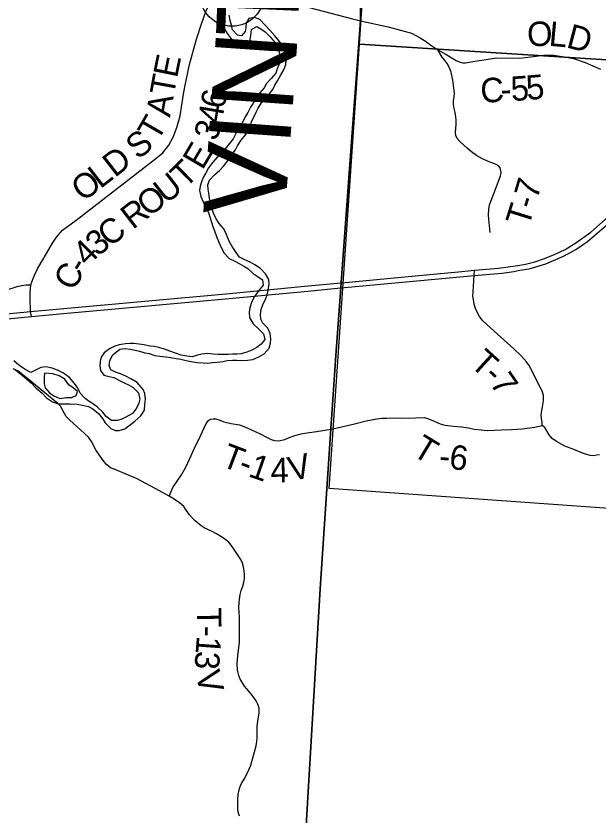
# Model space of a CAD drawing. Extents: x 0 to 34, y 0 to 22.
# Drawn here: x 3.455 to 4.807, y 17.141 to 18.997 of the extents above; entities that cross this region are included whole.
import ezdxf

# ---------------------------------------------------------------- set-up
doc = ezdxf.new("R2010")
doc.units = 0
for name, color, linetype in [('GM_X_Corporation', 7, 'Continuous'), ('GM_X_County_Road', 7, 'Continuous'), ('GM_X_County_Road_Text', 7, 'Continuous'), ('GM_X_County_Text', 7, 'Continuous'), ('GM_X_Major_River', 7, 'Continuous'), ('GM_X_State_Route', 7, 'Continuous'), ('GM_X_Township_Road', 7, 'Continuous'), ('GM_X_Township_Road_Text', 7, 'Continuous'), ('GM_X_Township_Text', 7, 'Continuous'), ('GM_X_Unincorporated', 7, 'Continuous')]:
    doc.layers.add(name, color=color, linetype=linetype)

msp = doc.modelspace()

# ---------------------------------------------------------------- linework, layer by layer
at = {"layer": 'GM_X_Corporation'}
msp.add_lwpolyline([(4.1215, 17.0136), (4.1603, 17.6679), (4.1853, 18.0392), (4.1964, 18.2095), (4.2079, 18.3668), (4.2088, 18.3789), (4.2282, 18.6426), (4.2537, 18.9868), (4.2536, 19.0552), (4.2737, 19.3421), (4.2893, 19.6309), (4.3029, 19.8336), (4.3134, 19.9898), (4.3401, 20.3869), (4.364, 20.7926), (4.3772, 20.9), (2.1, 20.9), (2.1, 14.9497)], dxfattribs=at)
for points in [[(5.342, 19.878), (5.2756, 18.8667), (4.2512, 18.9319), (4.3184, 19.9368)], [(4.2512, 18.9319), (5.2756, 18.8667), (5.2491, 18.5021), (5.2146, 18.0305), (5.1989, 17.8285), (4.1811, 17.9012)]]:
    msp.add_lwpolyline(points, close=True, dxfattribs=at)
at = {"layer": 'GM_X_County_Road'}
for points in [[(3.9168, 19.0437), (3.9261, 19.0496), (3.9355, 19.0554), (3.9447, 19.06), (3.9516, 19.0629), (3.9608, 19.0652), (3.9701, 19.0674), (3.9771, 19.0681), (3.9835, 19.0677), (3.992, 19.0674), (4.001, 19.065), (4.0168, 19.0614), (4.0442, 19.0511), (4.0739, 19.0399), (4.1079, 19.0272), (4.1213, 19.0223), (4.1351, 19.017), (4.2352, 18.9904), (4.2539, 18.9862)], [(3.5195, 18.4353), (3.5205, 18.4371), (3.5398, 18.4705), (3.5489, 18.484), (3.5628, 18.5), (3.5942, 18.5239), (3.6761, 18.5868), (3.7791, 18.6664), (3.7951, 18.68), (3.809, 18.6975), (3.8193, 18.716), (3.8275, 18.7388), (3.8353, 18.7655), (3.8433, 18.8163), (3.8461, 18.8329), (3.8573, 18.885), (3.8738, 18.9436), (3.8854, 18.9794), (3.8952, 19.0076), (3.9018, 19.0226), (3.9168, 19.0437)], [(4.2539, 18.9862), (4.3184, 18.9718), (4.3466, 18.9647), (4.372, 18.9572), (4.392, 18.9469), (4.4049, 18.9389), (4.4196, 18.9281), (4.4329, 18.9187), (4.4506, 18.9094), (4.4754, 18.8944), (4.4852, 18.89), (4.4916, 18.8889), (4.4971, 18.8887), (4.5192, 18.8922), (4.5407, 18.8958), (4.5545, 18.8982), (4.5694, 18.8999), (4.6224, 18.8994), (4.6356, 18.9007), (4.6552, 18.9033), (4.6788, 18.9062), (4.7019, 18.9062), (4.7269, 18.9029), (4.7478, 18.8988), (4.7752, 18.8893), (4.8104, 18.8742)], [(3.4904, 18.3), (3.4888, 18.3117), (3.4884, 18.3153), (3.4878, 18.3385), (3.4873, 18.3557), (3.4892, 18.3733), (3.4934, 18.3842), (3.4978, 18.3962), (3.5047, 18.4109), (3.5134, 18.425), (3.5195, 18.4353)]]:
    msp.add_lwpolyline(points, dxfattribs=at)
at = {"layer": 'GM_X_Major_River'}
for points in [[(3.9277, 19.0051), (3.9315, 18.9896), (3.9345, 18.9797), (3.9387, 18.9668), (3.9448, 18.9569), (3.9512, 18.9471), (3.9615, 18.9334), (3.9744, 18.9239), (3.988, 18.9265), (3.9975, 18.9387), (3.9998, 18.9523), (4.0014, 18.9656), (4.0131, 18.9732), (4.0226, 18.9675), (4.0325, 18.9603), (4.0442, 18.9489), (4.0556, 18.9352), (4.0621, 18.9254), (4.0655, 18.9125), (4.0677, 18.8988), (4.0662, 18.8882), (4.0609, 18.8745), (4.0574, 18.8643), (4.0464, 18.8525), (4.0362, 18.8404), (4.0301, 18.8309), (4.0198, 18.818), (4.0111, 18.8055), (4.0046, 18.7949), (3.9985, 18.7854), (3.9924, 18.7736), (3.9867, 18.7634), (3.9791, 18.7486), (3.9734, 18.7391), (3.9658, 18.7262), (3.9582, 18.7126), (3.9498, 18.7012), (3.9403, 18.6894), (3.9259, 18.675), (3.9167, 18.6644), (3.9084, 18.6542), (3.9015, 18.6447), (3.8947, 18.6322), (3.8886, 18.6223), (3.8848, 18.6128), (3.8817, 18.6022), (3.8806, 18.5927), (3.8832, 18.5787), (3.8889, 18.5661), (3.8954, 18.5525), (3.901, 18.5411), (3.9045, 18.5312), (3.9082, 18.5191), (3.9116, 18.5092), (3.9154, 18.499), (3.92, 18.4857), (3.9253, 18.4724), (3.9313, 18.4583), (3.9374, 18.447), (3.9495, 18.4344), (3.9624, 18.4283), (3.9723, 18.4234), (3.9833, 18.4169), (3.9928, 18.4116), (4.0046, 18.4002), (4.0167, 18.3919), (4.0262, 18.385), (4.0281, 18.3729), (4.0178, 18.36), (4.0079, 18.3463), (4.0018, 18.3346), (3.9973, 18.3205), (3.9957, 18.3099), (3.9965, 18.2978), (4.0048, 18.283), (4.0173, 18.2712), (4.0291, 18.2602), (4.0317, 18.2469), (4.0238, 18.2355), (4.0135, 18.2279), (4.0021, 18.2223), (3.9899, 18.2173), (3.9774, 18.2132), (3.9672, 18.2128), (3.9573, 18.2124), (3.947, 18.2121), (3.9239, 18.2121), (3.9121, 18.2128), (3.8996, 18.214), (3.8859, 18.2125), (3.8756, 18.2102), (3.8635, 18.2068), (3.851, 18.2083), (3.8381, 18.2106), (3.8248, 18.2148), (3.8115, 18.2194), (3.7993, 18.2243)], [(3.8263, 18.2027), (3.8373, 18.2007), (3.8494, 18.1981), (3.865, 18.195), (3.876, 18.1935), (3.8889, 18.1924), (3.8999, 18.192), (3.9109, 18.1935), (3.922, 18.1942), (3.9345, 18.1957), (3.9444, 18.1976), (3.9573, 18.1988), (3.9668, 18.1988), (3.9797, 18.198), (3.9914, 18.1984), (4.0044, 18.2006), (4.0177, 18.2067), (4.0302, 18.2131), (4.042, 18.2264), (4.045, 18.2378), (4.0462, 18.2477), (4.0443, 18.2606), (4.0386, 18.2731), (4.0276, 18.2845), (4.0227, 18.294), (4.0219, 18.3046), (4.0231, 18.3164), (4.0284, 18.3293), (4.0334, 18.3395), (4.0375, 18.3505), (4.0398, 18.3607), (4.0417, 18.3759), (4.0414, 18.3862), (4.0338, 18.3991), (4.022, 18.4116), (4.0088, 18.4203), (3.9978, 18.4264), (3.9856, 18.4317), (3.9735, 18.4378), (3.9655, 18.4485), (3.9564, 18.4625), (3.95, 18.4735), (3.9454, 18.4841), (3.9412, 18.4944), (3.9363, 18.5043), (3.9257, 18.516), (3.9189, 18.527), (3.9128, 18.5396), (3.9087, 18.5513), (3.906, 18.5616), (3.9034, 18.5749), (3.9019, 18.5859), (3.9003, 18.5957), (3.9, 18.6052), (3.9038, 18.6162), (3.9156, 18.6287), (3.9277, 18.6397), (3.9365, 18.6496), (3.9467, 18.6629), (3.954, 18.6739), (3.9639, 18.6868), (3.9688, 18.6962), (3.9772, 18.7095), (3.987, 18.7216), (3.9947, 18.7319), (3.9985, 18.7417), (4.0008, 18.7528), (4.0065, 18.7626), (4.0118, 18.774), (4.0164, 18.7835), (4.0232, 18.7952), (4.0323, 18.8047), (4.0418, 18.8157), (4.0502, 18.8271), (4.0548, 18.8369), (4.0616, 18.8468), (4.0692, 18.8608), (4.0764, 18.8722), (4.0806, 18.8851), (4.0818, 18.8961), (4.0807, 18.9098), (4.0742, 18.9257), (4.0659, 18.9383), (4.0549, 18.9515), (4.0435, 18.9641), (4.0325, 18.9762), (4.0204, 18.9891), (4.0082, 18.9941), (3.9949, 18.9918), (3.9885, 18.9804), (3.9877, 18.9709), (3.9862, 18.9615), (3.9778, 18.9516), (3.9683, 18.9531), (3.9573, 18.9653), (3.9547, 18.9759), (3.9516, 18.9865), (3.9494, 18.999)], [(3.7993, 18.2243), (3.7861, 18.2285), (3.7762, 18.2304), (3.7655, 18.2315), (3.7519, 18.2346), (3.7405, 18.2361), (3.7283, 18.2373), (3.7185, 18.2373), (3.7086, 18.2365), (3.6942, 18.2346), (3.6839, 18.2312), (3.6714, 18.2252), (3.6596, 18.2157), (3.6527, 18.2054), (3.6497, 18.1956), (3.6493, 18.1857), (3.6508, 18.1747), (3.6584, 18.1641), (3.6679, 18.1618), (3.6816, 18.1584), (3.6964, 18.1508), (3.7058, 18.1462), (3.7157, 18.1413), (3.7263, 18.1352), (3.7389, 18.123), (3.7419, 18.1086), (3.74, 18.0987), (3.7343, 18.0877), (3.7248, 18.0748), (3.7099, 18.0665), (3.7004, 18.062), (3.6906, 18.0585), (3.6761, 18.0589), (3.664, 18.0681), (3.6564, 18.0779), (3.6439, 18.0897), (3.6344, 18.0965), (3.6249, 18.1026), (3.6154, 18.1098), (3.6037, 18.1224), (3.5976, 18.1353), (3.59, 18.1455), (3.5794, 18.1577), (3.565, 18.1683), (3.551, 18.1752), (3.5388, 18.1801), (3.5244, 18.1835), (3.5126, 18.182), (3.5031, 18.1771), (3.4894, 18.1703), (3.4758, 18.1771), (3.4614, 18.1874), (3.4496, 18.1972)], [(3.4515, 18.1775), (3.461, 18.1703), (3.4742, 18.1593), (3.4898, 18.146), (3.5008, 18.1342), (3.5152, 18.1221), (3.5258, 18.1114), (3.5391, 18.1023), (3.5524, 18.0974), (3.5676, 18.0974), (3.5805, 18.0977), (3.5964, 18.0969), (3.6082, 18.0947), (3.6226, 18.0909), (3.6333, 18.0855), (3.6458, 18.0753), (3.6553, 18.0631), (3.6617, 18.0533), (3.6746, 18.0403), (3.6845, 18.0354), (3.694, 18.0358), (3.7069, 18.0396), (3.7164, 18.046), (3.7308, 18.057), (3.7445, 18.0699), (3.7525, 18.0828), (3.7536, 18.0961), (3.7548, 18.1086), (3.7537, 18.1215), (3.7499, 18.131), (3.7355, 18.1473), (3.7214, 18.1557), (3.7093, 18.1618), (3.6975, 18.1671), (3.6876, 18.1705), (3.6747, 18.1762), (3.6706, 18.1865), (3.6725, 18.1982), (3.6793, 18.2111), (3.6953, 18.224), (3.7082, 18.2255), (3.72, 18.2244), (3.731, 18.2221), (3.7412, 18.2198), (3.7534, 18.216), (3.7633, 18.2141), (3.7769, 18.2099), (3.7883, 18.2084), (3.8024, 18.2061), (3.8137, 18.2049), (3.8263, 18.2027)], [(3.5212, 18.1687), (3.5201, 18.1585), (3.5201, 18.1437), (3.5224, 18.1342), (3.5323, 18.1233), (3.5425, 18.1157), (3.5565, 18.11), (3.5713, 18.1123), (3.5842, 18.1123), (3.5893, 18.1145)], [(3.5893, 18.1145), (3.594, 18.1165), (3.5978, 18.126), (3.5872, 18.1347), (3.5777, 18.1415), (3.5678, 18.1544), (3.5546, 18.162), (3.5402, 18.1673), (3.5212, 18.1687)]]:
    msp.add_lwpolyline(points, dxfattribs=at)
at = {"layer": 'GM_X_State_Route'}
for points in [[(4.2081, 18.3662), (4.3931, 18.3837), (4.5176, 18.395), (4.5827, 18.4009), (4.6096, 18.4044), (4.6234, 18.4073), (4.6449, 18.411), (4.6841, 18.4225), (4.7244, 18.4397), (4.7534, 18.4558), (4.7801, 18.4743), (4.8348, 18.5208), (4.9519, 18.6244), (5.0029, 18.6705), (5.0757, 18.7346), (5.1002, 18.7546), (5.1243, 18.7729), (5.1439, 18.7876), (5.1801, 18.8119), (5.2033, 18.8272), (5.2305, 18.8431), (5.3733, 18.9281), (5.4683, 18.9843)], [(4.209, 18.3783), (4.2182, 18.3792), (4.3888, 18.3953), (4.4811, 18.4035), (4.5181, 18.4074), (4.5737, 18.4121), (4.6187, 18.4182), (4.6363, 18.4218), (4.6583, 18.4272), (4.6809, 18.4343), (4.7056, 18.4448), (4.7289, 18.4558), (4.7537, 18.4709), (4.7883, 18.4958), (4.8282, 18.531)], [(3.3064, 18.2941), (3.4888, 18.3117), (3.549, 18.3173), (3.9501, 18.3538), (4.1325, 18.3709), (4.209, 18.3783)], [(3.3079, 18.2824), (3.4904, 18.3), (3.5481, 18.3053), (3.9492, 18.3418), (4.1316, 18.3588), (4.2081, 18.3662)]]:
    msp.add_lwpolyline(points, dxfattribs=at)
at = {"layer": 'GM_X_Township_Road'}
for points in [[(4.5548, 18.4951), (4.5515, 18.5258), (4.5509, 18.5355), (4.5513, 18.5488), (4.5527, 18.5591), (4.5707, 18.6059), (4.5789, 18.6261), (4.5801, 18.6323), (4.5797, 18.6382), (4.5778, 18.645), (4.5739, 18.6496), (4.5685, 18.6524), (4.5485, 18.6608), (4.5354, 18.6668), (4.5232, 18.6735), (4.5113, 18.6819), (4.5011, 18.6907), (4.4934, 18.6978), (4.4839, 18.7062), (4.4781, 18.7131), (4.4753, 18.7202), (4.474, 18.7268), (4.4747, 18.737), (4.4757, 18.7456), (4.476, 18.7553), (4.4751, 18.7632), (4.4732, 18.7731), (4.4708, 18.7828), (4.4693, 18.7916), (4.4697, 18.8009), (4.4708, 18.8087), (4.4719, 18.819), (4.4704, 18.8302), (4.468, 18.8487), (4.4639, 18.8666), (4.4598, 18.8786), (4.4549, 18.8874), (4.4503, 18.8935), (4.443, 18.9019), (4.4329, 18.9187)], [(4.6667, 18.1436), (4.6616, 18.1539), (4.653, 18.1715), (4.645, 18.1863), (4.6386, 18.1951), (4.6267, 18.2089), (4.6093, 18.2249), (4.5639, 18.2661), (4.5375, 18.2902), (4.5301, 18.2998), (4.5245, 18.3103), (4.5206, 18.3183), (4.5172, 18.3289), (4.5157, 18.3396), (4.5145, 18.3476), (4.515, 18.3581), (4.5171, 18.3831), (4.5176, 18.395), (4.5181, 18.4074)], [(3.3454, 18.3407), (3.3656, 18.3459), (3.374, 18.3477), (3.4041, 18.354), (3.4403, 18.3643), (3.4503, 18.3671), (3.4576, 18.3694), (3.4673, 18.372)], [(3.4673, 18.372), (3.468, 18.3722), (3.4783, 18.3732), (3.4892, 18.3733)], [(3.9735, 17.1409), (3.97, 17.1499), (3.9696, 17.1586), (3.9696, 17.1702), (3.9697, 17.1795), (3.9702, 17.1912), (3.9723, 17.2021), (3.9746, 17.2094), (3.9781, 17.2165), (3.9837, 17.2266), (3.9924, 17.2425), (3.9993, 17.2591), (4.006, 17.2814), (4.0115, 17.3035), (4.0135, 17.3138), (4.0141, 17.3218), (4.0142, 17.3308), (4.0141, 17.3405), (4.0144, 17.3489), (4.0154, 17.3617), (4.019, 17.38), (4.019, 17.391), (4.0161, 17.4003), (4.0118, 17.4083), (4.0062, 17.416), (3.9988, 17.4258), (3.9903, 17.4359), (3.9851, 17.4426), (3.9798, 17.4503), (3.9747, 17.4583), (3.9715, 17.467), (3.9686, 17.4796), (3.9677, 17.4947), (3.9693, 17.5126), (3.9731, 17.5444), (3.9735, 17.6019), (3.9728, 17.6137), (3.972, 17.6244), (3.9726, 17.6376), (3.9729, 17.6436), (3.9745, 17.6552), (3.9767, 17.6643), (3.9807, 17.6745), (3.9833, 17.6829), (3.9848, 17.6919), (3.9851, 17.7003), (3.984, 17.7093), (3.9828, 17.7192), (3.9801, 17.7279), (3.9761, 17.7363), (3.9686, 17.748), (3.9561, 17.7662), (3.9485, 17.7761), (3.9384, 17.7845), (3.9299, 17.7898), (3.9197, 17.7958), (3.9095, 17.8013), (3.8994, 17.8061), (3.8909, 17.81), (3.8841, 17.8144), (3.8703, 17.8257), (3.8639, 17.8324), (3.8576, 17.8397), (3.8482, 17.8531), (3.8439, 17.8589), (3.8343, 17.8679), (3.8215, 17.8763), (3.8103, 17.8833), (3.7873, 17.8957), (3.7362, 17.9231), (3.6956, 17.9407), (3.686, 17.9442), (3.6799, 17.9465), (3.6743, 17.9492), (3.6694, 17.9526), (3.6644, 17.957), (3.6593, 17.9625), (3.6409, 17.9895), (3.6301, 18.0101), (3.6226, 18.0204), (3.6044, 18.0372), (3.579, 18.0602), (3.5715, 18.068), (3.5677, 18.0737), (3.5579, 18.092), (3.5521, 18.0984), (3.5216, 18.1228), (3.4786, 18.1583), (3.459, 18.1743), (3.4483, 18.1789)], [(4.8079, 17.9791), (4.8016, 17.9782), (4.7944, 17.9768), (4.7862, 17.9772), (4.7712, 17.9825), (4.749, 17.9914), (4.7275, 17.9994), (4.7082, 18.0098), (4.6988, 18.017), (4.6914, 18.0252), (4.6811, 18.0425), (4.6756, 18.0474), (4.6756, 18.0548), (4.6737, 18.0628), (4.6729, 18.0726), (4.6756, 18.0858), (4.6785, 18.1042), (4.678, 18.117), (4.675, 18.1272), (4.6684, 18.1401), (4.6667, 18.1436)], [(3.8103, 17.8833), (3.8149, 17.894), (3.8189, 17.9036), (3.8383, 17.9327), (3.8495, 17.952), (3.8688, 17.9943), (3.8826, 18.0232), (3.8924, 18.0434), (3.8958, 18.0514), (3.8991, 18.0558), (3.9022, 18.0595), (3.9071, 18.0622), (3.912, 18.0628), (3.9185, 18.0627), (3.9274, 18.0594), (3.9367, 18.0558), (3.9541, 18.052), (3.9734, 18.0484), (3.9908, 18.0419), (4.0215, 18.0278), (4.0362, 18.0199), (4.0463, 18.0146), (4.0545, 18.0122), (4.064, 18.0119), (4.078, 18.0149), (4.0871, 18.0186), (4.1015, 18.0242), (4.1135, 18.0274), (4.1197, 18.0287), (4.1516, 18.0331), (4.1855, 18.0386)], [(4.1855, 18.0386), (4.1999, 18.0416), (4.2372, 18.0503), (4.2668, 18.0577), (4.2914, 18.0628), (4.3044, 18.064), (4.3146, 18.0644), (4.3296, 18.0648), (4.3501, 18.064), (4.3817, 18.0647), (4.4022, 18.0654), (4.4115, 18.0628), (4.4244, 18.0572), (4.4388, 18.0511), (4.4494, 18.0482), (4.4566, 18.0468), (4.4693, 18.0458), (4.4882, 18.0443), (4.5042, 18.0416), (4.5178, 18.039), (4.534, 18.0369), (4.5479, 18.0357), (4.5644, 18.0365), (4.5806, 18.0371), (4.6042, 18.0375), (4.6288, 18.0396), (4.6583, 18.0431), (4.6756, 18.0474)]]:
    msp.add_lwpolyline(points, dxfattribs=at)
at = {"layer": 'GM_X_Township_Text'}
msp.add_lwpolyline([(4.3772, 20.9), (4.364, 20.7926), (4.3401, 20.3869), (4.3134, 19.9898), (4.3029, 19.8336), (4.2893, 19.6309), (4.2737, 19.3421), (4.2536, 19.0552), (4.2537, 18.9868), (4.2282, 18.6426), (4.2088, 18.3789), (4.2079, 18.3668), (4.1964, 18.2095), (4.1853, 18.0392), (4.1603, 17.6679), (4.1215, 17.0136)], dxfattribs=at)
at = {"layer": 'GM_X_Unincorporated'}
msp.add_circle((3.9557, 19.0478), 0.0744, dxfattribs=at)

# ---------------------------------------------------------------- texts
at = {"layer": 'GM_X_County_Road_Text'}
for s, rotation, p in [('O', 1.9565, (4.6411, 18.9266)), ('L', 354.76, (4.6892, 18.9284)), ('D', 345.1014, (4.729, 18.925)), ('E', 78.532, (3.8282, 18.8517)), ('T', 79.702, (3.8207, 18.8102)), ('5', 4.9574, (4.6402, 18.8022)), ('C', 3.077, (4.5333, 18.7957)), ('5', 4.016, (4.6043, 18.7997)), ('6', 79.576, (3.9378, 18.7799)), ('-', 3.3956, (4.5803, 18.7983)), ('A', 79.8433, (3.8119, 18.761)), ('4', 80.1171, (3.9318, 18.7455)), ('T', 59.9468, (3.7832, 18.7041)), ('3', 73.9149, (3.9206, 18.7054)), ('S', 38.0351, (3.7376, 18.6626)), ('E', 59.5716, (3.8873, 18.6379)), ('D', 37.7427, (3.6839, 18.6211)), ('T', 44.7663, (3.8473, 18.5954)), ('L', 37.7442, (3.6503, 18.5951)), ('O', 37.7501, (3.6108, 18.5645)), ('U', 37.9327, (3.8023, 18.5597)), ('O', 37.7167, (3.7626, 18.529)), ('R', 37.6583, (3.7256, 18.5005)), ('C', 37.5943, (3.6715, 18.4592)), ('3', 37.7317, (3.6439, 18.4378)), ('4', 45.1545, (3.6207, 18.4143)), ('C', 60.8089, (3.5884, 18.3568)), ('-', 59.2558, (3.611, 18.3971))]:
    msp.add_text(s, height=0.0568, rotation=rotation, dxfattribs=at).set_placement(p)
at = {"layer": 'GM_X_County_Text'}
for s, rotation, p in [('T', 87.4893, (4.1077, 18.9438)), ('N', 85.9918, (4.0957, 18.7713)), ('I', 85.8516, (4.09, 18.6935)), ('V', 85.8425, (4.0779, 18.5264))]:
    msp.add_text(s, height=0.1894, rotation=rotation, dxfattribs=at).set_placement(p)
at = {"layer": 'GM_X_Township_Road_Text'}
for s, rotation, p in [('7', 73.5821, (4.6637, 18.5698)), ('T', 72.6879, (4.6438, 18.5061)), ('-', 72.8192, (4.6565, 18.5468)), ('T', 317.7087, (4.5057, 18.187)), ('-', 317.457, (4.5371, 18.1585)), ('7', 304.5546, (4.5521, 18.1453)), ('T', 328.7783, (4.3712, 17.9799)), ('T', 339.2062, (3.9278, 17.9538)), ('6', 352.5426, (4.4574, 17.9473)), ('1', 340.7776, (3.991, 17.9299)), ('4', 1.1403, (4.0456, 17.9149)), ('V', 12.9473, (4.0933, 17.9172)), ('-', 355.5776, (4.4349, 17.949)), ('-', 339.3769, (3.9677, 17.9386)), ('T', 270.6686, (3.8742, 17.6248)), ('-', 269.0164, (3.8747, 17.5827)), ('1', 265.8332, (3.8744, 17.5602)), ('3', 266.1398, (3.8718, 17.525)), ('V', 283.4042, (3.871, 17.4715))]:
    msp.add_text(s, height=0.0568, rotation=rotation, dxfattribs=at).set_placement(p)

doc.saveas('drawing.dxf')
